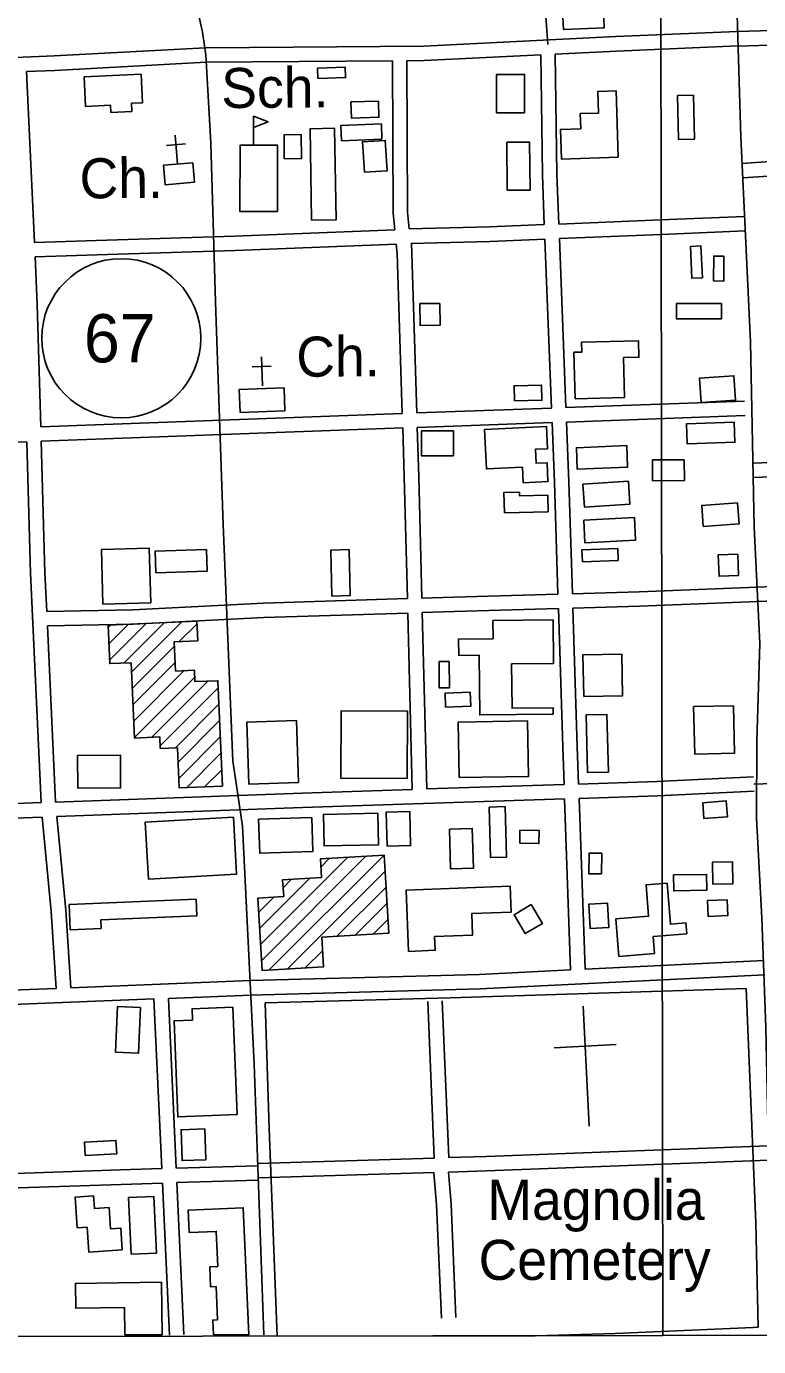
# Model space of a CAD drawing. Extents: x 3313447 to 3351316, y 703786 to 729172.
# Drawn here: x 3332031 to 3333549, y 709166 to 711903 of the extents above; entities that cross this region are included whole.
import ezdxf

# ---------------------------------------------------------------- set-up
doc = ezdxf.new("R2010")
doc.units = 0
for name, color, linetype in [('V-BLDG-IDEN', 7, 'Continuous'), ('V-BLDG-OTLN', 7, 'Continuous'), ('V-GRID-FRAM', 7, 'Continuous'), ('V-GRID-MAJR', 7, 'Continuous'), ('V-ROAD-CNTR', 7, 'Continuous'), ('V-ROAD-IDEN', 7, 'Continuous'), ('V-SITE-OTLN', 7, 'Continuous'), ('V-SITE-OTLN-IDEN', 7, 'Continuous')]:
    doc.layers.add(name, color=color, linetype=linetype)

msp = doc.modelspace()

# ---------------------------------------------------------------- linework, layer by layer
at = {"layer": 'V-BLDG-OTLN'}
for p, q in [((3332502, 711656.8), (3332502.1, 711716.8)), ((3332200.7, 710657.2), (3332205.5, 710662)), ((3332202.2, 710623.3), (3332242.5, 710663.6)), ((3332203.7, 710589.4), (3332279.5, 710665.2)), ((3332232.8, 710583.2), (3332316.4, 710666.8)), ((3332249.1, 710564.1), (3332353.4, 710668.4)), ((3332348.1, 710627.8), (3332385, 710664.6)), ((3332250.6, 710530.2), (3332338.2, 710617.9)), ((3332385.1, 710629.4), (3332386.4, 710630.7)), ((3332252, 710496.3), (3332339.7, 710584)), ((3332253.5, 710462.4), (3332358.5, 710567.4)), ((3332255, 710428.6), (3332380.1, 710553.6)), ((3332291, 710429.3), (3332407.5, 710545.8)), ((3332308.5, 710411.4), (3332428.7, 710531.5)), ((3332339.9, 710407.4), (3332430.1, 710497.6)), ((3332345.8, 710377.9), (3332431.6, 710463.8)), ((3332347.2, 710344), (3332433.1, 710429.9)), ((3332363.6, 710325), (3332434.5, 710396)), ((3332400.5, 710326.6), (3332436, 710362.1)), ((3332516.9, 710000.1), (3332697.5, 710180.6)), ((3332518.9, 709966.7), (3332735.1, 710182.9)), ((3332534, 709946.4), (3332772.8, 710185.2)), ((3332641.7, 710160.2), (3332659.8, 710178.3)), ((3332571.6, 709948.7), (3332774.8, 710151.9)), ((3332514.9, 710033.4), (3332618.7, 710137.2)), ((3332563.4, 710117.3), (3332581, 710134.9)), ((3332674.9, 710016.6), (3332776.9, 710118.6)), ((3332512.8, 710066.7), (3332543.9, 710097.8)), ((3332712.6, 710018.9), (3332778.9, 710085.3)), ((3332750.2, 710021.2), (3332780.9, 710051.9)), ((3332609.3, 709951), (3332645.4, 709987.1)), ((3332647, 709953.3), (3332647.4, 709953.8)), ((3332235.1, 709190.2), (3332312.9, 709190.3)), ((3332492.4, 709190.6), (3332418.8, 709190.4))]:
    msp.add_line(p, q, dxfattribs=at)
for points in [[(3333142.7, 711935.4), (3333144.3, 711896.8), (3333229.1, 711900.2), (3333227.6, 711938.8)], [(3332635.1, 711794.9), (3332634.3, 711816.3), (3332692.1, 711818.5), (3332692.9, 711797)], [(3332151.2, 711798.5), (3332268.9, 711803.8), (3332271.5, 711744.8), (3332249.2, 711743.8), (3332249.9, 711726.8), (3332205.9, 711724.8), (3332205.2, 711739.5), (3332153.9, 711737.2)], [(3333005.9, 711724), (3333064, 711724), (3333063.9, 711803.5), (3333005.8, 711803.4)], [(3333258, 711631.9), (3333140.3, 711628), (3333138.3, 711689.6), (3333180.5, 711691), (3333179.5, 711722.2), (3333217, 711723.4), (3333215.5, 711768.2), (3333253.5, 711769.4)], [(3333380.9, 711759.8), (3333413.9, 711760.5), (3333415.9, 711669.6), (3333382.9, 711668.9)], [(3332703.8, 711746.4), (3332704.8, 711713.1), (3332761.9, 711714.8), (3332760.9, 711748.1)], [(3332502.1, 711716.8), (3332532.1, 711705.2), (3332502.1, 711693.7)], [(3332768.3, 711669.4), (3332767, 711701.1), (3332683.1, 711697.7), (3332684.4, 711665.9)], [(3332565.8, 711628.8), (3332601.3, 711629), (3332601, 711678.7), (3332565.6, 711678.5)], [(3332622.5, 711501.1), (3332673.5, 711502.1), (3332670.1, 711691.8), (3332619.1, 711690.9)], [(3332473.9, 711519.4), (3332551.6, 711519.4), (3332551.7, 711656.7), (3332474, 711656.8)], [(3332731.8, 711601), (3332727.8, 711663.8), (3332775.2, 711666.7), (3332779.1, 711603.9)], [(3333075.3, 711563.9), (3333028, 711563.5), (3333027.2, 711662.9), (3333074.5, 711663.3)], [(3332379.5, 711580.1), (3332376, 711620.4), (3332315.3, 711615.3), (3332318.8, 711574.9)], [(3333407.9, 711447), (3333429.7, 711448), (3333432.8, 711382), (3333411, 711381)], [(3333477, 711375.2), (3333455.8, 711375.3), (3333456.2, 711426.8), (3333477.3, 711426.7)], [(3332888.1, 711328.9), (3332846.8, 711328.4), (3332847.4, 711283), (3332888.7, 711283.6)], [(3333472.1, 711328.3), (3333472.1, 711296.6), (3333378.7, 711296.6), (3333378.7, 711328.3)], [(3333168.5, 711131.2), (3333271.1, 711133.7), (3333269.1, 711216.5), (3333301.1, 711217.3), (3333300.3, 711251), (3333182.3, 711248.2), (3333182.8, 711227.8), (3333166.2, 711227.4)], [(3333429.8, 711123.2), (3333426.4, 711173.8), (3333498, 711178.7), (3333501.4, 711128)], [(3332474, 711102.5), (3332472.4, 711150.5), (3332565.2, 711153.7), (3332566.8, 711105.8)], [(3333043, 711126.8), (3333042.3, 711158.1), (3333099.3, 711159.3), (3333099.9, 711128)], [(3332981.2, 711067.7), (3333109.6, 711073.7), (3333111.7, 711027.6), (3333086.5, 711026.5), (3333087.8, 710997.5), (3333110.5, 710998.6), (3333112.3, 710959.3), (3333061.3, 710957), (3333059.8, 710989.1), (3332985, 710985.6)], [(3333498.6, 711082.9), (3333500.1, 711041), (3333401.2, 711037.5), (3333399.7, 711079.4)], [(3332916.3, 711012.7), (3332916.3, 711064.5), (3332850.2, 711064.4), (3332850.3, 711012.6)], [(3333173.2, 710985.1), (3333171.4, 711029.6), (3333275.7, 711034), (3333277.5, 710989.5)], [(3333395, 711004.6), (3333395.3, 710961.6), (3333329.5, 710961.2), (3333329.3, 711004.2)], [(3333279.1, 710960.5), (3333282.3, 710912.9), (3333187.9, 710906.4), (3333184.7, 710954)], [(3333022.1, 710894.8), (3333112.8, 710896.7), (3333112, 710931.2), (3333053.4, 710929.9), (3333053.2, 710937.7), (3333021.2, 710937.1)], [(3333505.6, 710915.3), (3333508.7, 710872), (3333434.4, 710866.6), (3333431.3, 710909.9)], [(3333186.5, 710879.3), (3333189, 710832.3), (3333294.1, 710838), (3333291.6, 710884.9)], [(3332288.8, 710707.9), (3332189.9, 710705.3), (3332187, 710818.5), (3332285.9, 710821.1)], [(3332404.5, 710818.6), (3332405.8, 710773.7), (3332299.6, 710770.5), (3332298.2, 710815.3)], [(3332664.4, 710722.1), (3332702.3, 710723), (3332700.1, 710818.3), (3332662.3, 710817.4)], [(3333183.7, 710793.3), (3333182.9, 710818), (3333257, 710820.5), (3333257.9, 710795.9)], [(3333505.8, 710809.2), (3333507.8, 710765), (3333467.3, 710763.2), (3333465.3, 710807.4)], [(3332437.5, 710328.2), (3332428, 710546.6), (3332380.4, 710544.6), (3332379.4, 710568.3), (3332340.4, 710566.6), (3332337.8, 710627.3), (3332386.5, 710629.4), (3332384.7, 710669.7), (3332200.5, 710661.8), (3332204, 710581.9), (3332248.2, 710583.8), (3332255, 710427.7), (3332307.7, 710430), (3332308.7, 710406.1), (3332344.5, 710407.6), (3332348.1, 710324.3)], [(3333037.1, 710581.5), (3333038.1, 710489.5), (3333123.1, 710490.4), (3333123.3, 710477.4), (3332971, 710475.7), (3332969.6, 710599.6), (3332927.5, 710599.1), (3332927.1, 710632.7), (3332998.7, 710633.5), (3332998.3, 710671.2), (3333123, 710672.5), (3333124, 710582.5)], [(3332907.9, 710586.5), (3332886.9, 710586.5), (3332887, 710531.7), (3332908, 710531.8)], [(3333186.9, 710513.8), (3333185, 710600.1), (3333265.4, 710601.8), (3333267.3, 710515.5)], [(3332900.1, 710491.6), (3332899, 710520.6), (3332951.1, 710522.6), (3332952.2, 710493.6)], [(3333497, 710494.7), (3333414.4, 710492.9), (3333416.6, 710394.3), (3333499.1, 710396.1)], [(3332820.7, 710344.1), (3332683.3, 710344.3), (3332683.5, 710483.8), (3332820.9, 710483.6)], [(3333191.8, 710475.8), (3333234.8, 710476.8), (3333237.7, 710357.2), (3333194.7, 710356.2)], [(3332595, 710335.4), (3332492.5, 710332), (3332488.3, 710460.7), (3332590.8, 710464.1)], [(3332928.2, 710345.7), (3332926.3, 710460.9), (3333070.3, 710463.3), (3333072.2, 710348.1)], [(3332137.6, 710323.6), (3332226.4, 710324.3), (3332225.9, 710392.5), (3332137.1, 710391.8)], [(3332779, 710203.7), (3332827.6, 710204.9), (3332825.9, 710275.5), (3332777.2, 710274.3)], [(3332990.2, 710284.6), (3333023.4, 710285.6), (3333026.5, 710181), (3332993.4, 710180)], [(3333433.2, 710293.5), (3333435.8, 710260.8), (3333484.7, 710264.6), (3333482.1, 710297.3)], [(3332460.2, 710263.8), (3332467, 710145.5), (3332284.3, 710135), (3332277.5, 710253.4)], [(3332622.8, 710262.8), (3332625, 710192.6), (3332514.9, 710189), (3332512.6, 710259.2)], [(3332760, 710271.9), (3332761.4, 710206.4), (3332648.4, 710204), (3332647, 710269.5)], [(3332908.1, 710239), (3332955.5, 710240.4), (3332957.9, 710157.9), (3332910.5, 710156.5)], [(3333053.8, 710209.6), (3333054.2, 710236.4), (3333094, 710235.9), (3333093.7, 710209)], [(3332772.8, 710185.2), (3332782.7, 710023.2), (3332643.7, 710014.7), (3332647.4, 709953.4), (3332520.2, 709945.6), (3332511.1, 710095.8), (3332564.6, 710099), (3332562.4, 710133.8), (3332643, 710138.7), (3332640.7, 710177.1)], [(3333223.4, 710146), (3333197.5, 710146.4), (3333198.2, 710189.2), (3333224.1, 710188.8)], [(3333494.9, 710170.7), (3333453.5, 710170.1), (3333454.1, 710124.8), (3333495.4, 710125.3)], [(3333372.6, 710144), (3333373.2, 710110.9), (3333441.8, 710112), (3333441.3, 710145.1)], [(3333034, 710120.4), (3332818.4, 710112.1), (3332823.2, 709985.4), (3332878.6, 709987.6), (3332877.5, 710016.1), (3332956.1, 710019.1), (3332954.4, 710063.8), (3333036, 710067)], [(3333359.4, 710127.1), (3333366.4, 710041.7), (3333398.5, 710044.4), (3333400.3, 710021.9), (3333330.3, 710016.1), (3333333.2, 709981), (3333259.7, 709975), (3333253.3, 710052.6), (3333321, 710058.1), (3333315.7, 710123.6)], [(3332382.9, 710093.5), (3332119.9, 710082.4), (3332122.1, 710030.4), (3332185.9, 710033.1), (3332185.2, 710050.7), (3332384.3, 710059.2)], [(3333238.7, 710034.6), (3333200, 710032.6), (3333197.4, 710083.3), (3333236.1, 710085.3)], [(3333483.9, 710092.4), (3333485.3, 710059.6), (3333444.7, 710057.8), (3333443.2, 710090.6)], [(3333077.8, 710082.5), (3333042.2, 710061.3), (3333065.4, 710022.4), (3333101, 710043.5)], [(3332267.9, 709869.1), (3332263.6, 709774.2), (3332216, 709776.3), (3332220.2, 709871.2)], [(3332459.4, 709869.6), (3332467.8, 709646.9), (3332344.9, 709642.3), (3332337.3, 709841.5), (3332375.4, 709842.9), (3332374.5, 709866.4)], [(3332152.9, 709562.1), (3332218.4, 709565.9), (3332216.8, 709593.3), (3332151.4, 709589.5)], [(3332402.9, 709553.4), (3332353.9, 709551.8), (3332351.7, 709615.5), (3332400.8, 709617.2)], [(3332230, 709366.8), (3332160.4, 709362), (3332156.9, 709413.3), (3332136.4, 709411.9), (3332132, 709475.8), (3332170.3, 709478.4), (3332172.1, 709452.3), (3332202.4, 709454.4), (3332205.4, 709410.3), (3332226.9, 709411.8)], [(3332248.2, 709357.5), (3332242.8, 709475.1), (3332295.1, 709477.5), (3332300.6, 709359.9)]]:
    msp.add_lwpolyline(points, close=True, dxfattribs=at)
for points in [[(3332418.8, 709190.4), (3332417.4, 709221), (3332427.3, 709221.5), (3332424.2, 709290.4), (3332413, 709289.9), (3332411.2, 709331.3), (3332427.9, 709332.1), (3332424.7, 709404.9), (3332368.8, 709402.5), (3332366.7, 709448.9), (3332480.8, 709454), (3332492.4, 709190.6)], [(3332311.5, 709299.5), (3332132.7, 709297), (3332133.4, 709245.5), (3332234.3, 709246.8), (3332235.1, 709190.2)], [(3332312.9, 709190.3), (3332311.5, 709299.5)]]:
    msp.add_lwpolyline(points, dxfattribs=at)
at = {"layer": 'V-GRID-FRAM'}
msp.add_lwpolyline([(3317576.9, 727351), (3317595.4, 709166), (3349105.8, 709211.8), (3349071.4, 727396.8), (3317576.9, 727351)], dxfattribs=at)
at = {"layer": 'V-GRID-MAJR'}
msp.add_line((3333350.6, 709188.9), (3333341.8, 715247.1), dxfattribs=at)
at = {"layer": 'V-ROAD-CNTR'}
for points in [[(3332821.6, 717425.9), (3332837.1, 717075.6), (3332867, 716504.6), (3332903.6, 715833.6), (3332980.1, 714334.9), (3333075, 712390.5), (3333094.9, 712117.1), (3333109.3, 711904.2), (3333112.3, 711865.9)], [(3333491.9, 713728.4), (3333470.3, 713659.3), (3333447.3, 713576.6), (3333417.2, 713465), (3333405, 713407.4), (3333397.4, 713365.3), (3333399.8, 713315.9), (3333413.3, 713252.8), (3333426.9, 713140.5), (3333433.6, 713027.1), (3333461.5, 712649.6), (3333483.5, 712248.6), (3333504.1, 711949.9), (3333512.2, 711673.9), (3333532.1, 711248.8), (3333540.2, 710864.8), (3333551.9, 710623.7), (3333545.5, 710421.9), (3333544.6, 710261.3), (3333555.9, 710054.2), (3333564.4, 709827.7), (3333575.4, 709301.8), (3333584.1, 709192.1)], [(3332236.6, 712760.9), (3332249.2, 712630.8), (3332266.2, 712495.2), (3332319.8, 712242.1), (3332333.8, 712169.3), (3332363, 712041.5), (3332396.3, 711891.4), (3332403.3, 711844)], [(3332403.2, 711859), (3332855.1, 711862.1), (3333253, 711881.9), (3333505.6, 711892.4)], [(3333505.8, 711892.4), (3333851.5, 711903), (3333901.6, 711904.8)], [(3333506.7, 711862.4), (3333852.5, 711873), (3333905.7, 711874.9)], [(3332008.2, 711838.8), (3332088.4, 711842), (3332402.4, 711859)], [(3332403.3, 711844), (3332413.2, 711661), (3332423.1, 711331.4), (3332439.3, 710870.1), (3332459, 710380), (3332467, 710329.4), (3332478.8, 710245), (3332503.5, 709751.9), (3332523.3, 709190.6)], [(3332820.1, 711831.9), (3332856, 711832.1), (3333097.6, 711844.2)], [(3333104.9, 711492.1), (3333100.9, 711595.6), (3333097.6, 711844.2)], [(3333127.5, 711845.6), (3333254.3, 711851.9), (3333506.9, 711862.5)], [(3333134.9, 711493.3), (3333130.9, 711596.4), (3333127.5, 711845.6)], [(3332031.3, 711809.7), (3332089.8, 711812), (3332404.1, 711829.1)], [(3332031.3, 711809.7), (3332047.7, 711455.1)], [(3332403.4, 711829), (3332790.1, 711831.7)], [(3332790.1, 711831.7), (3332791.5, 711516.1), (3332795, 711481.5)], [(3332820.1, 711831.9), (3332821.5, 711517.7), (3332825, 711483.3)], [(3333514.5, 711619), (3333700.4, 711631.9), (3333913.8, 711637.9)], [(3333516.6, 711589), (3333701.8, 711601.9), (3333914.8, 711608)], [(3333134.9, 711493.3), (3333346.3, 711502), (3333520, 711509.1)], [(3332047.7, 711455.1), (3332198.2, 711460.2), (3332462.5, 711468.3), (3332795, 711481.5)], [(3332825, 711483.3), (3332991.3, 711487.4), (3333104.9, 711492.1)], [(3332828, 711453.3), (3332992.3, 711457.4), (3333106.1, 711462.1)], [(3332829.3, 711453.4), (3332840.4, 711101.6)], [(3333119.7, 711111.8), (3333106.1, 711462.1)], [(3333136.1, 711463.3), (3333347.5, 711472), (3333521.3, 711479.2)], [(3333149.7, 711112.9), (3333136.1, 711463.3)], [(3332049.1, 711425.1), (3332199.2, 711430.2), (3332463.6, 711438.3), (3332798, 711451.6)], [(3332049.1, 711425.1), (3332053.7, 711326.4), (3332060.9, 711073.1)], [(3332798, 711451.6), (3332800, 711432.5), (3332810.4, 711100.5)], [(3333149.7, 711112.9), (3333519.9, 711126.4)], [(3332060.9, 711073.1), (3332810.4, 711100.5)], [(3332840.4, 711101.6), (3333119.7, 711111.8)], [(3332061.8, 711043.1), (3332811.4, 711070.5)], [(3332811.4, 711070.5), (3332814.5, 710969.4), (3332820.9, 710716.9)], [(3332841.3, 711071.6), (3333120.9, 711081.8)], [(3332841.3, 711071.6), (3332844.5, 710970.2), (3332850.9, 710717.8)], [(3333133, 710726.1), (3333125.7, 710958), (3333120.9, 711081.8)], [(3333150.9, 711082.9), (3333521, 711096.4)], [(3333163, 710727), (3333155.7, 710959.1), (3333150.9, 711082.9)], [(3331673.9, 711029.5), (3332031.8, 711042.1)], [(3332031.8, 711042.1), (3332039.6, 710769.4), (3332061.6, 710293.8)], [(3332061.8, 711043.1), (3332069.6, 710770.5), (3332073.3, 710690.2)], [(3333537.2, 710997.8), (3333935.1, 711012.8)], [(3333538.3, 710967.8), (3333936.1, 710982.8)], [(3333543.7, 710740.5), (3333900.5, 710753.4), (3333943.9, 710755.2)], [(3332073.3, 710690.2), (3332251.6, 710693.7), (3332522.5, 710707.6), (3332820.9, 710716.9)], [(3332850.9, 710717.8), (3332917.3, 710719.9), (3333133, 710726.1)], [(3333163, 710727), (3333301.5, 710731), (3333546.4, 710740.6)], [(3333544.8, 710710.5), (3333901.7, 710723.4), (3333996.9, 710727.4)], [(3332074.7, 710660.2), (3332252.6, 710663.7), (3332523.7, 710677.6), (3332821.7, 710686.9)], [(3332821.7, 710686.9), (3332831, 710321.1)], [(3332851.7, 710687.8), (3332918.2, 710689.9), (3333134, 710696.1)], [(3332851.7, 710687.8), (3332861, 710322.1)], [(3333145.7, 710331.4), (3333143, 710409.5), (3333134, 710696.1)], [(3333163.9, 710697), (3333302.5, 710701), (3333547.5, 710710.6)], [(3333175.7, 710332.4), (3333172.9, 710410.5), (3333163.9, 710697)], [(3332074.7, 710660.2), (3332091.6, 710294.9)], [(3333539.3, 710332.3), (3336912.6, 710452.2)], [(3332861, 710322.1), (3333145.7, 710331.4)], [(3333175.7, 710332.4), (3333338.3, 710337.7), (3333538.6, 710347.3)], [(3332091.6, 710294.9), (3332602.6, 710313.6), (3332831, 710321.1)], [(3333176.8, 710302.4), (3333339.5, 710307.7), (3333540, 710317.3)], [(3331701.2, 710281), (3331904.7, 710288), (3332061.6, 710293.8)], [(3332093.9, 710264.9), (3332603.7, 710283.7), (3333146.8, 710301.4)], [(3333159.4, 709946.8), (3333146.8, 710301.4)], [(3333189.4, 709948.3), (3333176.8, 710302.4)], [(3331720.7, 710251.7), (3331905.8, 710258), (3332063.9, 710263.8)], [(3332093, 709908.7), (3332082.7, 710068.2), (3332063.9, 710263.8)], [(3332123, 709909.9), (3332112.6, 710070.6), (3332093.9, 710264.9)], [(3333189.4, 709948.3), (3333560.7, 709966.7)], [(3332123, 709909.9), (3332495, 709924.7)], [(3332495.2, 709924.7), (3332970.7, 709937.4), (3333159.4, 709946.8)], [(3332496, 709894.7), (3332971.8, 709907.5), (3333562.2, 709936.7)], [(3331737.9, 709896.2), (3332001.1, 709905.1), (3332093, 709908.7)], [(3332325.5, 709887.9), (3332496.2, 709894.7)], [(3331931.3, 709872.7), (3332002.2, 709875.1), (3332295.5, 709886.7)], [(3332295.5, 709886.7), (3332311.7, 709534.9)], [(3332325.5, 709887.9), (3332341.6, 709535.8)], [(3332863.1, 709881.4), (3332876.8, 709557)], [(3332893.1, 709882.7), (3332906.7, 709558)], [(3332906.7, 709558), (3332984, 709560.3), (3333569.2, 709582.4)], [(3332341.6, 709535.8), (3332511, 709540.9)], [(3332510.8, 709545.9), (3332876.8, 709557)], [(3332905.9, 709527.9), (3332985, 709530.3), (3333570.4, 709552.4)], [(3331947.8, 709522.8), (3332226.4, 709532.4), (3332311.7, 709534.9)], [(3332343, 709505.9), (3332511.9, 709510.9)], [(3332511.8, 709515.9), (3332875.9, 709527)], [(3332875.9, 709527), (3332881.6, 709459.7), (3332891.7, 709224.7)], [(3332905.9, 709527.9), (3332911.5, 709461.6), (3332921.7, 709226)], [(3331949.7, 709492.8), (3332227.4, 709502.4), (3332313, 709505)], [(3332313, 709505), (3332327.5, 709189.6)], [(3332343, 709505.9), (3332357.5, 709191)]]:
    msp.add_lwpolyline(points, dxfattribs=at)
at = {"layer": 'V-ROAD-IDEN'}
msp.add_circle((3332227.9, 711256.5), 165, dxfattribs=at)
at = {"layer": 'V-SITE-OTLN'}
for p, q in [((3332344.7, 711617.8), (3332339.6, 711677.6)), ((3332361.3, 711659.3), (3332321.4, 711655.9)), ((3332520.3, 711157.9), (3332518.2, 711217.8)), ((3332538.9, 711198.5), (3332498.9, 711197.1)), ((3332909.5, 709889.4), (3333349.3, 709903.2)), ((3333349.3, 709903.2), (3333523.7, 709908.3)), ((3333523.7, 709908.3), (3333543.7, 709422.6)), ((3332526.4, 709878.9), (3332909.5, 709889.4)), ((3332534.5, 709618.3), (3332526.4, 709878.9)), ((3333197.8, 709622.8), (3333185.4, 709871.8)), ((3333253.8, 709792), (3333125.2, 709785.6)), ((3332551.3, 709187.8), (3332534.5, 709618.3)), ((3333543.7, 709422.6), (3333548.3, 709206.4)), ((3333085.7, 709188.5), (3332551.3, 709187.8)), ((3333252, 709193.4), (3333085.7, 709188.5)), ((3333538, 709205.9), (3333252, 709193.4)), ((3333548.3, 709206.4), (3333538, 709205.9))]:
    msp.add_line(p, q, dxfattribs=at)

# ---------------------------------------------------------------- texts
at = {"layer": 'V-BLDG-IDEN'}
msp.add_text('Sch.', height=83, rotation=0.3995, dxfattribs=at).set_placement((3332435.4, 711733.7))
at = {"layer": 'V-ROAD-IDEN'}
msp.add_text('67', height=100, dxfattribs=at).set_placement((3332150.3, 711206.5))
at = {"layer": 'V-SITE-OTLN-IDEN'}
for p in [(3332141.6, 711546.4), (3332591, 711176.6)]:
    msp.add_text('Ch.', height=83, rotation=0.3995, dxfattribs=at).set_placement(p)
for s, p in [('Magnolia', (3332986.9, 709428.8)), ('Cemetery', (3332968.7, 709304.3))]:
    msp.add_text(s, height=83, dxfattribs=at).set_placement(p)

doc.saveas('drawing.dxf')
